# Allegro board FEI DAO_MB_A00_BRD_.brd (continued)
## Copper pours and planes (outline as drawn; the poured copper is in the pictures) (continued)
+VCHGR on BOTTOM (solid shape): 66.66,9.08 66.66,4.57 66.49,4.4 64.95,4.4 64.65,4.7 61.45,4.7 61.14,5.01 61.14,9.06 61.31,9.23 66.51,9.23
+VCHGR on BOTTOM (solid shape): 29.32,16.06 29.32,15.43 27.95,15.43 27.59,15.07 27.95,14.72 29.32,14.72 29.32,14.12 29.18,13.98 28.7,13.98 28.26,13.55 28.26,11.05 27.93,10.72 25.9,10.72 25.47,11.16 25.47,15.21 26.37,16.11 29.27,16.11
+VCHGR on IN2: 58.78,4.77 58.16,5.39 38.84,5.39 37.93,6.31 25.41,6.31 24.72,6.99 24.72,12.42 25.22,12.92 28.02,12.92 28.3,12.65 28.3,11.19 28.66,10.82 47.21,10.82 48.32,9.71 59.33,9.71 59.34,9.71 60.29,9.71 60.53,9.47 63.55,9.47 64.91,8.12 64.91,5.03 64.65,4.77
+VCHGR_B on TOP (solid shape): 33.64,14.72 33.64,12.72 33.5,12.58 32.97,12.58 31.97,13.58 31.09,13.58 30.92,13.75 30.92,14.78 31.01,14.87 33.5,14.87
+VCHGR_B on TOP (solid shape): 24.39,24.01 24.39,22.22 23.74,21.57 23.74,19.8 22.05,18.11 20.5,18.11 20.16,18.45 20.16,22.1 20.36,22.3 22.04,22.3 22.59,22.84 22.59,24.06 22.62,24.1 24.3,24.1
+VCHGR_B on BOTTOM (solid shape): 22.26,21.45 22.26,18.31 21.24,17.29 18.38,17.29 18.26,17.41 18.26,20.83 19.22,21.79 21.91,21.79
+VCHGR_B on IN4 (solid shape): 33.61,14.51 33.61,13.45 33.51,13.34 31.63,13.34 31.4,13.57 31.4,14.49 31.65,14.74 33.38,14.74
+VCHGR_B on IN4 (solid shape): 22.47,18.25 22.47,17.59 22.07,17.18 21.53,17.18 20.54,18.17 20.54,18.68 20.69,18.83 21.89,18.83
+VCHGR_L on BOTTOM (solid shape): 28.09,19.76 28.15,19.69 28.21,19.64 29.63,18.22 31.07,18.22 31.16,18.13 31.23,17.7 31.67,17.62 32.59,16.7 32.59,14.06 32.44,13.9 30.51,13.9 30.33,14.08 30.33,14.72 31.7,14.72 32.06,15.07 31.7,15.43 30.33,15.43 30.33,15.48 29.41,16.41 27.97,16.41 27.05,17.33 24.14,17.33 24.06,17.41 24.06,20.89 24.13,20.96 26.89,20.96
+VDISPLAY_VCC on BOTTOM (solid shape): 82.08,100.97 82.08,100.48 81.87,100.28 80.82,100.28 80.62,100.08 80.62,99.52 80.12,99.01 80.12,96.6 79.86,96.35 79.21,96.35 78.94,96.62 78.94,99.95 80.2,101.21 81.84,101.21
+VDISPLAY_VCC on IN2 (solid shape): 81.2,103.06 81.2,101.85 81.98,101.08 81.98,100.44 81.68,100.15 79.94,100.15 79.66,100.43 79.66,103.04 79.82,103.2 81.07,103.2
+VR_CAP on TOP (solid shape): 298.67,62.19 298.67,61.17 298.61,61.11 296.58,61.11 296.39,61.3 296.39,62.19 296.64,62.44 298.42,62.44
+VR_CAP on BOTTOM (solid shape): outline of 367 points within 290.84,58.96 298.2,63.23
-DCIN_JACK on TOP (solid shape): 19.51,75.67 19.51,71.72 19.31,71.52 16.86,71.52 16.47,71.91 16.47,75.04 16.7,75.27 18.09,75.27 18.54,75.71 19.46,75.71
-DCIN_JACK on BOTTOM (solid shape): 21.65,73.53 21.65,69.23 21.41,68.99 18.88,68.99 18.67,69.2 18.67,70.41 18.66,70.42 18.66,71.11 17.61,72.16 17.61,74.98 17.97,75.34 19.84,75.34
BOOT on TOP (solid shape): 33.81,18.17 33.81,17.08 33.91,16.99 33.91,16.83 34.78,15.96 34.78,15.23 34.75,15.2 33.77,15.2 33.66,15.31 33.66,15.88 33.56,15.98 33.56,18.17 33.61,18.22 33.76,18.22
BOOT1G on BOTTOM (solid shape): 142.39,82.68 142.39,82.57 141.24,81.43 141.24,80.98 141.02,80.75 140.15,80.75 140.11,80.8 140.11,81.93 140.25,82.07 140.76,82.07 141.43,82.74 142.33,82.74
BOOT_1.5V on TOP (solid shape): 35.46,64.86 37.37,64.86 37.42,64.81 37.42,64.7 37.37,64.65 35.82,64.65 35.16,63.99 34.37,63.99 34.3,64.07 34.3,65.08 34.41,65.2 35.12,65.2
BST_3V on TOP (solid shape): 252.31,9.29 253.05,9.29 253.68,8.67 253.68,7.47 253.65,7.45 253.05,7.45 253.02,7.48 253.02,7.98 251.98,9.03 251.06,9.03 250.97,9.11 250.97,9.22 251.06,9.31 252.3,9.31
BST_5V on TOP (solid shape): 248.09,9.26 248.09,9.1 248.01,9.03 247.09,9.03 246.99,8.92 246.98,8.92 246.07,8.01 246.07,8 246.06,7.99 246.06,7.7 245.82,7.46 244.91,7.46 244.87,7.5 244.87,8.34 244.91,8.38 245.89,8.38 245.9,8.39 245.91,8.39 246.83,9.31 248.04,9.31
BST_+V1.05S_VCCPP on TOP (solid shape): 123.69,10.21 123.69,10.03 123.46,9.8 123.46,8.98 123.08,8.6 121.38,8.6 121.27,8.7 121.27,9.88 121.44,10.06 122.52,10.06 122.76,10.3 123.6,10.3
BST_+V1.05SP on BOTTOM (solid shape): 156.08,64.05 156.08,63.35 156.01,63.28 155.02,63.28 154.16,62.42 153.28,62.42 153.2,62.49 153.2,63.08 154.26,64.14 155.99,64.14
CHAGER_SRC on TOP (solid shape): 25.42,27.87 25.42,27.09 25.56,26.95 26.51,26.95 26.55,26.91 26.55,24.6 26.35,24.39 22.54,24.39 22.29,24.15 22.29,22.97 22.05,22.73 20.59,22.73 20.37,22.95 20.37,26.77 20.74,27.14 22.95,27.14 23.84,28.03 25.27,28.03
CHAGER_SRC on BOTTOM (solid shape): 23.73,27.28 23.73,23.1 23.26,22.63 20.98,22.63 20.61,23 20.61,27.13 21,27.52 23.48,27.52
CHG_LGATE on TOP (solid shape): 19.85,19.93 19.85,16.79 19.7,16.63 18.4,16.63 18.18,16.85 18.18,19.87 18.31,20 19.77,20
CHG_LGATE on TOP (solid shape): 31.88,19.11 31.88,18.96 31.81,18.88 30.71,18.88 30.36,18.53 29.42,18.53 29.37,18.58 29.37,19.06 29.47,19.16 31.83,19.16
CHG_LGATE on IN1 (solid shape): 20.55,17.51 20.55,16.63 20.43,16.51 18.79,16.51 18.65,16.65 18.65,17.51 18.76,17.62 20.44,17.62
CHG_LGATE on IN1 (solid shape): 30.64,18.95 30.64,18.11 30.51,17.98 28.1,17.98 27.91,18.17 27.91,18.88 28.15,19.12 30.46,19.12
CHG_UGATE on TOP (solid shape): 26.32,23.94 26.32,22.9 26.13,22.7 24.73,22.7 24.58,22.86 24.58,23.99 24.68,24.09 26.17,24.09
CHG_UGATE on TOP (solid shape): 33.33,18.14 33.33,16.8 33.43,16.7 33.43,15.91 33.48,15.86 33.48,15.04 33.44,15 32.88,15 32.82,15.06 32.82,15.87 32.91,15.96 32.91,16.74 33.05,16.88 33.05,18.16 33.12,18.23 33.25,18.23
CHG_UGATE on IN4 (solid shape): 26.26,23.19 26.26,21.69 26.07,21.5 25.13,21.5 25.02,21.6 25.02,23.16 25.15,23.29 26.15,23.29
CHG_UGATE on IN4 (solid shape): 33.53,16.67 33.53,15.83 33.33,15.63 31.65,15.63 31.35,15.94 31.35,16.82 31.48,16.95 33.25,16.95
DH_1.5V on TOP (solid shape): 25.08,61.01 25.08,60.74 24.85,60.51 22.81,60.51 22.66,60.67 22.66,61.05 22.78,61.16 24.92,61.16
DH_1.5V on TOP (solid shape): 36.43,65.26 37.34,65.26 37.42,65.19 37.42,65.11 37.34,65.03 35.62,65.03 34.93,65.72 34.93,66.08 35.13,66.28 35.41,66.28
DH_1.5V on IN1 (solid shape): 25.37,61.62 25.37,60.6 25.24,60.47 22.89,60.47 22.7,60.67 22.7,61.55 22.89,61.74 25.24,61.74
DH_1.5V on IN1 (solid shape): 35.91,65.87 35.91,65.17 35.59,64.86 33.43,64.86 33.24,65.05 33.24,66.06 33.5,66.32 35.46,66.32
DL_1.5V on TOP (solid shape): 30.89,67.09 30.89,66.48 30.71,66.3 28.58,66.3 28.45,66.43 28.45,66.96 28.68,67.19 30.79,67.19
DL_1.5V on TOP (solid shape): 37.52,68.39 37.52,66.96 37.72,66.76 37.72,65.82 37.65,65.75 37.57,65.75 37.17,66.15 37.17,66.58 36.81,66.94 36.81,68.42 36.92,68.54 37.37,68.54
DL_1.5V on IN1 (solid shape): 37.43,68.54 37.43,67.52 37.24,67.33 32.67,67.33 31.72,66.38 29.88,66.38 29.75,66.51 29.75,67.21 31.27,68.73 37.24,68.73
LG_3V on TOP (solid shape): 255.65,13.29 255.65,12.5 255.4,12.25 252.93,12.25 252.03,11.36 252.03,10.63 251.94,10.54 251.06,10.54 250.97,10.62 250.97,10.74 251.06,10.83 251.06,11.85 251.84,12.62 251.84,12.75 252.51,13.42 255.52,13.42
LG_5V on TOP (solid shape): 247.3,10.85 247.99,10.85 248.07,10.77 248.07,10.61 248,10.54 246.91,10.54 246.86,10.59 246.29,10.59 245.56,9.86 244.77,9.86 244.61,10.01 244.61,10.31 245.5,11.2 246.96,11.2
LG_5V on BOTTOM (solid shape): 237.11,12.5 237.11,11.91 236.23,11.03 235.73,11.03 235.61,11.16 235.61,11.94 236.34,12.67 236.94,12.67
LG_5V on IN1 (solid shape): 245.84,10.97 245.84,9.98 245.74,9.88 244.74,9.88 244.6,10.02 244.6,10.43 244.16,10.88 244.16,11.59 244.34,11.77 245.05,11.77
LG_5V on IN1 (solid shape): 239.25,13.78 239.25,12.88 239.11,12.74 237.69,12.74 236.47,11.53 236.22,11.53 236.04,11.7 236.04,12.51 237.39,13.85 237.67,13.85 237.67,13.85 239.17,13.85
LG_+V1.05S_VCCPP on TOP (solid shape): 123.69,12.72 123.69,12.08 123.6,12 122.84,12 122.22,12.62 122.22,12.77 122.36,12.91 123.5,12.91
LG_+V1.05S_VCCPP on TOP (solid shape): 119.09,4.28 119.09,3.83 119.73,3.2 119.73,2.84 119.59,2.7 118.67,2.7 118.59,2.79 118.59,3.33 118.68,3.42 118.68,4.25 118.78,4.34 119.03,4.34
LG_+V1.05S_VCCPP on IN1 (solid shape): 119.73,3.93 119.73,2.77 119.61,2.65 118.73,2.65 118.59,2.79 118.59,3.93 118.83,4.17 119.49,4.17
LG_+V1.05S_VCCPP on IN1 (solid shape): 123.49,12.66 123.49,12.11 123.28,11.89 121.95,11.89 121.83,11.77 121.61,11.77 121.01,12.37 121.01,12.56 121.34,12.89 123.26,12.89
LG_+V1.05SP on TOP (solid shape): 154.86,54.74 154.86,54.36 154.77,54.26 152.2,54.26 152.06,54.4 152.06,54.72 152.19,54.85 154.75,54.85
LG_+V1.05SP on BOTTOM (solid shape): 158.31,64.05 158.31,63.5 158.64,63.17 158.64,62.17 158.55,62.08 158.01,62.08 157.92,62.18 157.92,63.09 157.79,63.22 157.79,64.04 157.87,64.12 158.24,64.12
LG_+V1.05SP on IN1 (solid shape): 154.92,54.72 154.92,53.73 154.84,53.65 152.68,53.65 152.53,53.81 152.53,54.75 152.63,54.85 154.79,54.85
LG_+V1.05SP on IN1 (solid shape): 158.73,63.18 158.73,60.64 158.49,60.4 157.83,60.4 157.61,60.62 157.61,62.42 157.92,62.73 157.92,63.22 158.04,63.33 158.58,63.33
LGATE1 on BOTTOM (solid shape): 147.67,77.3 147.67,75.39 147.1,74.83 146.78,74.83 146.46,75.14 146.46,77.24 146.59,77.37 147.6,77.37
LGATE1 on BOTTOM (solid shape): 145.5,82.38 145.5,81.04 145.8,80.73 145.8,79.97 145.65,79.82 145.22,79.82 145.13,79.91 145.13,80.89 145.27,81.04 145.27,82.38 145.32,82.43 145.45,82.43
LGATE1 on IN1 (solid shape): 145.75,80.87 145.75,79.92 147.1,78.57 147.1,76.33 146.99,76.22 146.46,76.22 146.27,76.41 146.27,78.06 144.81,79.52 144.81,80.92 144.87,80.99 145.64,80.99
LGATE1G on BOTTOM (solid shape): 129,93.3 129,92.1 128.49,91.59 127.98,91.59 127.6,91.97 127.6,93.3 127.79,93.49 128.81,93.49
LGATE1G on BOTTOM (solid shape): 134.71,92.4 134.71,91.53 134.52,91.34 133.37,91.34 133.2,91.51 133.2,92.45 133.35,92.61 134.51,92.61
LGATE1G on BOTTOM (solid shape): 140.82,83.96 142.31,83.96 142.38,83.89 142.38,83.79 142.32,83.73 139.55,83.73 139.5,83.78 139.5,84.19 139.58,84.26 140.52,84.26
LGATE1G on IN1 (solid shape): 129,93.3 129,92.89 129.6,92.29 133.69,92.29 133.91,92.52 134.55,92.52 134.78,92.29 134.78,91.46 134.46,91.15 127.55,91.15 127.23,91.46 127.23,93.18 127.48,93.43 128.87,93.43
LGATE1G on IN1 (solid shape): 140.69,84.08 140.69,83.89 140.51,83.71 140.49,83.71 140.41,83.72 140.33,83.7 139.89,83.7 139.83,83.71 139.77,83.72 139.72,83.71 139.44,84 136.98,84 136.71,84.26 136.71,85.21 137.02,85.52 139.26,85.52
LX_3V on TOP (solid shape): 258.73,10.75 260.57,10.75 260.66,10.66 260.66,9.58 260.56,9.47 255.25,9.47 254.58,10.14 252.34,10.14 252.24,10.04 251.06,10.04 250.98,10.12 250.98,10.23 251.05,10.3 252.03,10.3 252.34,10.62 252.34,11.32 252.84,11.82 257.66,11.82
LX_3V on BOTTOM (solid shape): 256.99,13.14 256.99,11.44 257.16,11.26 258.22,11.26 258.35,11.14 258.35,9.48 256.82,7.96 256.82,5.78 256.7,5.66 254.25,5.66 254.19,5.72 254.19,10.96 255.12,11.89 255.12,12.98 255.37,13.23 256.9,13.23
LX_5V on TOP (solid shape): 246.89,10.31 248.02,10.31 248.07,10.26 248.07,10.08 248.02,10.03 246.51,10.03 245.73,9.25 245.73,9.25 245.68,9.21 244.45,9.21 244.09,9.57 243.55,9.57 243.48,9.64 243.48,10.22 243.57,10.31 244.27,10.31 244.46,10.12 244.46,9.97 244.7,9.74 244.71,9.73 245.61,9.73 245.64,9.75 245.83,9.85 245.93,10.04 245.94,10.05 246.32,10.44 246.76,10.44
LX_5V on BOTTOM (solid shape): 229.37,13.99 229.37,12.3 231.12,10.55 236.63,10.55 236.99,10.2 236.99,9.74 237.42,9.31 238.51,9.31 238.66,9.15 238.66,6.77 238.43,6.54 229.57,6.54 228.63,7.48 228.63,10 227.77,10.87 227.77,13.97 228.03,14.23 229.13,14.23
LX_5V on IN1 (solid shape): 235.71,10.56 235.71,9.5 235.21,9 234.32,9 234.08,9.23 234.08,10.32 234.6,10.84 235.43,10.84
LX_5V on IN1 (solid shape): 244.4,10.25 244.4,9.96 244.64,9.73 245.71,9.73 245.83,9.61 245.83,9.32 245.73,9.23 243.65,9.23 243.48,9.4 243.48,10.32 243.58,10.42 244.23,10.42
MCARD_WWAN_PWREN# on TOP (solid shape): 314.76,36.28 314.76,32.74 314.55,32.53 313.54,32.53 313.44,32.63 313.44,36.3 313.6,36.46 314.58,36.46
PBATT+_C on BOTTOM (solid shape): 60.1,7.13 60.1,1.55 59.85,1.29 57.69,1.29 57.24,1.74 57.24,4.21 55.85,5.61 55.85,7.6 56.02,7.77 59.46,7.77
PCH_AZ_SYNC_Q on BOTTOM (solid shape): 180.28,32.8 180.28,30.98 180.12,30.82 178.8,30.82 178.62,31 178.62,32.63 178.67,32.69 179.27,32.69 179.54,32.96 180.12,32.96
PHASE1 on BOTTOM (solid shape): 145.9,82.38 145.9,81.44 146.72,80.63 146.72,79.21 146.61,79.1 146.07,79.1 145.98,79.19 145.98,80.76 145.67,81.06 145.67,82.38 145.75,82.46 145.83,82.46
PHASE1 on BOTTOM (solid shape): 147.73,73.3 147.73,73.3 148.08,72.95 149.36,72.95 149.36,72.95 149.47,72.95 149.68,72.74 149.68,68.9 150.7,67.88 150.7,63.67 150.46,63.42 146.13,63.42 146,63.54 146,64.86 148.66,64.86 148.66,65.62 146,65.62 146,66.18 142.75,69.43 142.75,70.52 143.04,70.8 143.04,72.35 142.59,72.79 141.65,72.79 141.47,72.97 141.47,73.63 141.53,73.68 142.21,73.68 142.57,74.04 146.99,74.04
PHASE1 on IN4 (solid shape): 147.86,80.67 147.86,80.16 147.54,79.84 146.14,79.84 146.02,79.97 146.02,80.79 146.21,80.99 147.54,80.99
PHASE1 on IN4 (solid shape): 148.05,71.59 148.05,71.14 147.73,70.83 146.27,70.83 146.08,71.02 146.08,71.97 146.4,72.29 147.35,72.29
PHASE1G on TOP (solid shape): 125.63,89.31 125.63,86.5 125.45,86.32 124.44,86.32 121.74,89.02 121.73,89.02 120.88,89.87 120.88,92.47 121.15,92.74 122.21,92.74
PHASE1G on BOTTOM (solid shape): 141.41,83.55 142.32,83.55 142.38,83.49 142.38,83.38 142.32,83.32 141,83.32 140.77,83.09 139.63,83.09 139.45,83.09 139.32,82.97 138.38,82.97 138.28,83.07 138.28,83.47 138.38,83.58 141.38,83.58
PHASE1G on BOTTOM (solid shape): 123.41,95.22 123.41,91.59 124.17,90.83 128.43,90.83 128.71,90.54 133.6,90.54 133.9,90.24 133.9,86 133.84,85.94 126.12,85.94 125.9,85.72 125.9,85.09 125.82,85.01 123.69,85.01 123.28,85.42 123.28,87.48 120.88,89.88 120.88,90.91 120.4,91.39 119.96,91.39 119.91,91.44 119.91,93.92 119.14,93.92 119.14,91.45 119.08,91.39 117.57,91.39 117.33,91.63 117.33,95.69 117.81,96.17 122.46,96.17
PHASE1G on IN4 (solid shape): 139.55,83.58 140.65,83.58 140.7,83.53 140.7,83.17 140.62,83.09 138.13,83.09 138.11,83.12 138.11,83.91 138.28,84.08 139.05,84.08
PHASE1G on IN4 (solid shape): 124.38,89.21 124.38,87.69 124.19,87.5 124.19,86.5 124.11,86.42 123.25,86.42 122.97,86.7 122.97,87.72 123.44,88.19 123.44,89.16 123.59,89.32 124.27,89.32
REGCTL_PNP10 on TOP (solid shape): 287.22,79.02 287.22,78.03 287.28,77.97 287.28,77.35 287.2,77.26 286.82,77.26 286.69,77.39 286.69,77.75 287,78.06 287,78.93 287,79.01 287.06,79.07 287.16,79.07
SNUB_1.5V on TOP (solid shape): 29.38,69.34 29.38,67.71 29.24,67.57 27.32,67.57 27.08,67.8 27.08,69.19 27.4,69.51 29.21,69.51
SNUB_3V on BOTTOM (solid shape): 253.94,14.14 253.94,13.52 254.34,13.12 254.34,11.52 254.2,11.38 252.95,11.38 252.77,11.57 252.77,12.83 252.64,12.97 252.64,14.15 252.76,14.28 253.8,14.28
SNUB_5V on BOTTOM (solid shape): 233.01,14.16 233.01,12.57 232.83,12.39 230.71,12.39 230.6,12.5 230.6,14.13 230.79,14.32 232.85,14.32
SW_1.5V on TOP (solid shape): 36.95,66.61 36.95,66.16 37.42,65.69 37.42,65.52 37.34,65.44 36.45,65.44 35.44,66.46 34.73,66.46 34.65,66.53 34.65,68.04 34.83,68.22 35.34,68.22
SW_1.5V on TOP (solid shape): 26.93,69.45 26.93,67.15 27.26,66.82 27.84,66.82 28.03,66.63 28.03,63.78 27.91,63.65 25.43,63.65 25.24,63.46 25.24,61.62 25.01,61.39 21.41,61.39 20.99,61.81 20.99,66.38 21.43,66.82 22.33,66.82 24.72,66.82 25.58,66.82 25.96,67.21 25.96,69.76 26.24,70.04 26.35,70.04
SW_1.5V on BOTTOM (solid shape): 28.03,66.57 28.03,62.44 27.59,62 21.56,62 21.37,62.19 21.37,63.14 21.56,63.33 21.56,65.75 21.75,65.94 25.37,65.94 26.19,66.76 27.84,66.76
SW_+V1.05S_VCCPP on TOP (solid shape): 120.43,11.45 120.43,10.88 120.33,10.79 119.54,10.79 118.71,9.96 118.71,8.85 119.65,7.91 120.89,7.91 121.02,7.78 121.02,5.91 120.87,5.76 119.94,5.76 119.16,4.98 116.11,4.98 115.98,5.1 115.98,10.9 116.66,11.58 120.3,11.58
SW_+V1.05S_VCCPP on BOTTOM (solid shape): 124.91,8.5 124.91,6.82 124.72,6.63 122.56,6.63 122.14,6.21 122.14,4.38 122.05,4.29 117.13,4.29 116.85,4.57 116.85,7.03 116.45,7.43 116.45,8.48 116.77,8.8 124.61,8.8
SW_+V1.05SP on TOP (solid shape): 156.58,58.65 156.58,57.81 156.83,57.57 158.23,57.57 158.37,57.43 158.37,54.33 158.31,54.28 155.49,54.28 155.33,54.44 155.33,56.87 154.83,57.37 154.83,58.63 154.97,58.77 156.47,58.77
SW_+V1.05SP on BOTTOM (solid shape): 157.1,64.04 157.1,62.67 157.46,62.32 157.46,61.71 157.71,61.45 160.2,61.45 160.31,61.34 160.31,60.37 160.23,60.28 157.99,60.28 157.1,59.4 157.1,57.85 157.46,57.49 157.46,55.74 156.62,54.9 155.91,54.9 155.91,54.9 155.68,54.9 155.52,55.06 155.52,55.12 153.33,57.31 152.71,57.31 152.43,57.59 152.43,60.03 153.02,60.61 155.68,60.61 155.94,60.87 155.94,61.59 156.01,61.67 156.58,61.67 156.8,61.88 156.8,64.04 156.88,64.12 157.03,64.12
UG_3V on TOP (solid shape): 261.4,10.46 261.4,8.53 261.26,8.4 258.55,8.4 258.41,8.53 258.41,9.1 258.54,9.23 260.7,9.23 260.89,9.42 260.89,10.5 260.99,10.6 261.26,10.6
UG_3V on TOP (solid shape): 253.46,9.85 253.46,9.52 253.36,9.42 253.02,9.42 252.94,9.43 252.85,9.42 252.37,9.42 252.24,9.55 251.04,9.55 250.97,9.61 250.97,9.73 251.05,9.8 252.24,9.8 252.41,9.97 253.35,9.97
UG_3V on IN1 (solid shape): 254.53,10.21 254.53,9.58 254.31,9.37 252.44,9.37 252.29,9.52 252.29,10.18 252.55,10.44 254.3,10.44
UG_3V on IN1 (solid shape): 259.61,9 259.61,8.19 259.45,8.04 257.8,8.04 257.73,8.11 257.73,8.95 257.93,9.15 259.45,9.15
UG_5V on TOP (solid shape): 246.98,9.8 248.02,9.8 248.07,9.75 248.07,9.57 248.02,9.52 246.87,9.52 245.86,8.51 244.6,8.51 244.55,8.56 244.55,9.01 244.62,9.08 245.49,9.08 245.53,9.08 245.7,9.08 245.78,9.12 246.56,9.9 246.88,9.9
UG_5V on BOTTOM (solid shape): 238.74,10.45 238.74,9.69 238.59,9.53 237.62,9.53 237.57,9.59 237.57,10.5 237.65,10.58 238.61,10.58
UG_5V on IN1 (solid shape): 238.77,10.41 238.77,8.9 238.71,8.85 237.57,8.85 237.47,8.95 237.47,10.41 237.66,10.6 238.58,10.6
UG_5V on IN1 (solid shape): 245.82,8.88 245.82,8 245.63,7.81 243.81,7.81 243.63,8 243.63,8.76 243.7,8.83 244.48,8.83 244.7,9.05 245.64,9.05
UG_+V1.05S_VCCPP on TOP (solid shape): 121.03,5.38 121.03,4.25 121.1,4.19 121.1,3.74 120.93,3.58 120.04,3.58 119.88,3.74 119.88,4.14 120,4.27 120,5.4 120.12,5.52 120.88,5.52
UG_+V1.05S_VCCPP on TOP (solid shape): 122.56,10.78 123.63,10.78 123.7,10.7 123.7,10.55 123.63,10.47 122.48,10.47 122.22,10.21 121.1,10.21 120.99,10.33 120.99,10.87 121.38,11.27 122.07,11.27
UG_+V1.05S_VCCPP on IN1 (solid shape): 122.2,10.69 122.2,8.98 122.01,8.79 121.19,8.79 121.06,8.91 121.06,10.69 121.19,10.82 122.08,10.82
UG_+V1.05S_VCCPP on IN1 (solid shape): 121.32,4.67 121.32,4.45 121.14,4.26 121.14,3.72 120.97,3.55 120.07,3.55 119.93,3.7 119.93,4.6 120.49,5.15 120.84,5.15
UG_+V1.05SP on TOP (solid shape): 157.94,58.77 157.94,57.82 157.83,57.72 156.97,57.72 156.82,57.87 156.82,58.68 157.08,58.94 157.12,58.98 157.72,58.98
UG_+V1.05SP on BOTTOM (solid shape): 156.6,64.04 156.6,62.07 156.51,61.99 156.11,61.99 156.01,62.09 156.01,63.08 156.29,63.36 156.29,64.04 156.37,64.12 156.52,64.12
UG_+V1.05SP on IN1 (solid shape): 156.62,63.14 156.62,59.37 156.85,59.14 157.71,59.14 157.87,58.99 157.87,57.9 157.76,57.79 156.14,57.79 155.66,58.28 155.66,61.48 155.92,61.74 155.92,61.76 156.01,61.85 156.01,63.13 156.14,63.26 156.51,63.26
UGATE1 on BOTTOM (solid shape): 146.37,82.29 146.75,82.29 147.35,81.7 147.35,81.24 147.22,81.11 146.46,81.11 146.06,81.52 146.06,82.36 146.13,82.43 146.23,82.43
UGATE1 on BOTTOM (solid shape): 149.68,75.35 149.68,73.74 149.49,73.56 148.59,73.56 148.33,73.82 148.33,75.27 148.65,75.59 149.45,75.59
UGATE1 on IN4 (solid shape): 149.99,76.59 149.99,74.61 149.89,74.51 149.1,74.51 148.95,74.66 148.95,76.57 149.08,76.69 149.89,76.69
UGATE1 on IN4 (solid shape): 148.37,82.05 148.37,81.37 148.01,81.01 147.7,81.01 147.59,81.11 146.49,81.11 146.46,81.14 146.46,82.08 146.64,82.26 148.16,82.26
UGATE1G on TOP (solid shape): 125.64,85.53 125.64,84.27 125.47,84.11 124.44,84.11 124.3,84.25 124.3,85.49 124.49,85.68 125.48,85.68
UGATE1G on BOTTOM (solid shape): 142.39,83.08 142.39,83 142.33,82.94 141.43,82.94 140.82,82.33 139.65,82.33 139.53,82.46 139.53,82.81 139.68,82.97 139.69,82.97 139.79,82.95 139.89,82.97 140.33,82.97 140.43,82.95 140.53,82.97 140.9,82.97 141.08,83.14 142.32,83.14
UGATE1G on IN4 (solid shape): 126.04,85.96 126.04,84.39 125.76,84.11 124.38,84.11 124.14,84.35 124.14,85.86 124.44,86.17 125.84,86.17
UGATE1G on IN4 (solid shape): 139.79,82.95 139.89,82.97 140.33,82.97 140.43,82.95 140.53,82.97 140.62,82.97 140.7,82.89 140.7,82.03 140.62,81.95 138.23,81.95 138.16,82.03 138.16,82.89 138.23,82.97 139.7,82.97
VFB on TOP (solid shape): 31.4,24.17 31.4,22.18 31.88,21.7 31.88,20.97 31.81,20.89 30.76,20.89 30.68,20.98 30.68,21.98 30.64,22.02 30.64,24.22 30.72,24.3 31.27,24.3
VLDOIN_1.5V on TOP (solid shape): 36.43,64.45 37.34,64.45 37.39,64.4 37.39,64.3 37.34,64.25 36.43,64.25 35.67,63.48 35.41,63.48 35.31,63.59 35.31,63.92 35.9,64.5 36.38,64.5
VLDOIN_1.5V on TOP (solid shape): 38.33,60.13 38.33,59.74 38.36,59.71 38.86,59.71 38.87,59.7 38.87,59.56 38.86,59.55 38.36,59.55 38.33,59.52 38.33,59.06 38.2,58.93 37.17,58.93 37.05,59.05 37.05,60.04 37.18,60.17 38.28,60.17
VSB_N_001 on TOP (solid shape): 39.67,74.57 39.67,73.75 39.27,73.35 37.83,73.35 37.41,72.92 35.32,72.92 35.21,73.03 35.21,73.58 35.4,73.77 36.2,73.77 36.46,74.03 36.46,74.85 36.72,75.11 39.14,75.11
N41545453 on TOP (solid shape): 32.82,18.15 32.82,16.88 32.77,16.82 32.77,16.23 31.92,15.38 30.08,15.38 30,15.46 30,15.95 30.43,16.38 30.44,16.38 30.48,16.42 31.92,16.42 32.54,17.04 32.54,18.15 32.63,18.23 32.74,18.23
N41545632 on TOP (solid shape): 26.59,22.48 26.59,20.98 26.42,20.81 23.95,20.81 23.89,20.86 23.89,21.52 24.9,22.53 26.54,22.53
N41557433 on BOTTOM (solid shape): 128.31,85.44 128.31,83.85 128.31,83.8 128.2,83.69 126.41,83.69 126.22,83.89 126.22,85.53 126.33,85.65 128.11,85.65
N41557582 on BOTTOM (solid shape): 139.39,82.52 139.39,80.84 139.3,80.76 138.51,80.76 138.36,80.91 138.36,82.55 138.45,82.64 139.26,82.64
N41558133 on BOTTOM (solid shape): 149.29,79.87 149.29,78.97 149.21,78.89 149.21,78.89 147.12,78.89 146.98,79.04 146.98,79.85 147.1,79.97 149.19,79.97
N41563825 on BOTTOM (solid shape): 136.82,3.88 136.82,2.52 136.42,2.12 134.85,2.12 134.69,2.27 134.69,3.84 134.85,4 136.7,4
N41572339 on BOTTOM (solid shape): 155.61,61.76 155.61,61.02 155.56,60.97 153.24,60.97 153.12,61.09 153.12,61.77 153.28,61.93 155.43,61.93
N41572388 on BOTTOM (solid shape): 160.84,58.51 160.84,56.41 160.65,56.22 159.45,56.22 159.32,56.35 159.32,57.11 159.16,57.27 158.66,57.27 158.48,57.45 158.48,58.72 158.59,58.82 160.52,58.82
N41580322 on TOP (solid shape): 34.37,67.09 34.37,66.41 34.02,66.05 34.02,64.2 33.84,64.02 33.03,64.02 32.92,64.12 32.92,64.81 32.59,65.14 32.59,67.05 32.74,67.19 34.27,67.19
N42519434 on TOP (solid shape): 29.12,74.1 29.12,72.99 29,72.87 26.44,72.87 26.44,73.44 26.47,73.46 27.29,73.46 27.56,73.74 27.56,74.02 27.7,74.16 29.07,74.16

Small or netless copper shapes (teardrops, artwork), in the pictures only: 58 on TOP, 223 on BOTTOM

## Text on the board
Ref Des/Silkscreen Bottom: H17 | H16 | H14 | H13 | A | INSERT | RELEASE | TAA | M-SATA | WLAN | WIGIG | LTE | WWAN
User.Comments: LA8831P | 2013-07-13 | 2012-07-13 | QCZ00 | kerry
Ref Des/Silkscreen Top: 4 | 2 | 1 | 3
BODY_CENTER: GNDA | +5v_run | GND | +PWR_SRC | +3.3V_RUN | +3.3V_ALW | +5V_ALW | +1.05v_run_vtt | +VCC_GFXCORE | +vcc_sa | +VCC_CORE | +1.05v_run
User.40: 4 / 4.6 | Width/space | 3.5 / 9 | 85 ohm
User.42: FIGURE | SIZE | 9.0 | 10.0 | 20.0 | 28.0 | 30.0 | 35.0 | 39.0 | 79.0 | 91.0 | 110.0 | 126.0 | 150.0 | 43.0 | 47.0 | 59.0 | 63.0 | 71.0 | 55.0x24.0 | 59.0x24.0 | 71.0x31.0 | 93.0x31.0 | 98.0x24.0 | 98.0x79.0 | 102.0x31.0 | 110.0x31.0 | 110.0x91.0 | DRILL CHART: TOP to BOTTOM | ALL UNITS ARE IN MILS | PLATED | NON-PLATED | QTY | 818 | 4932 | 19 | 33 | 7 | 17 | 12 | 1 | 4 | 8 | 2 | 5
